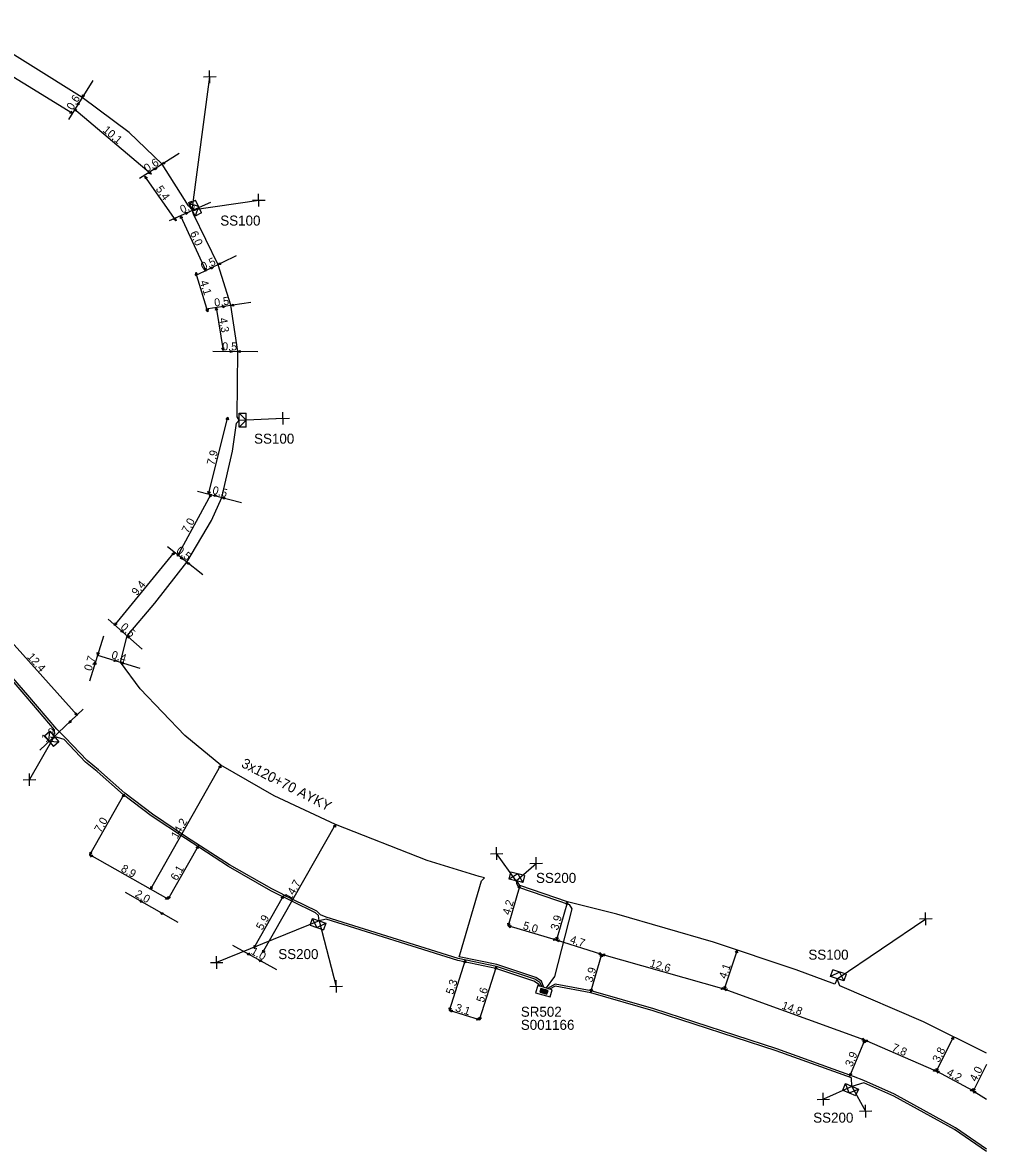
# Model space of a CAD drawing. Extents: x -762504 to -761250, y -1152974 to -1152253.
# Drawn here: x -761345.8 to -761250, y -1152498.2 to -1152386 of the extents above; entities that cross this region are included whole.
import ezdxf

# ---------------------------------------------------------------- set-up
doc = ezdxf.new("R2010")
doc.units = 0
for name, color, linetype in [('Vrstva 28', 7, 'Continuous'), ('Vrstva 29', 7, 'Continuous'), ('Vrstva 30', 7, 'Continuous'), ('Vrstva 31', 7, 'Continuous'), ('Vrstva 33', 7, 'Continuous'), ('Vrstva 34', 7, 'Continuous'), ('Vrstva 40', 7, 'Continuous'), ('Vrstva 5', 7, 'Continuous'), ('Vrstva 59', 7, 'Continuous'), ('Vrstva 6', 7, 'Continuous')]:
    doc.layers.add(name, color=color, linetype=linetype)

msp = doc.modelspace()

# ---------------------------------------------------------------- linework, layer by layer
at = {"layer": 'Vrstva 28'}
for points in [[(-761294.578, -1152481.71), (-761294.785, -1152482.431)], [(-761293.136, -1152482.124), (-761294.578, -1152481.71)], [(-761294.271, -1152481.989), (-761294.375, -1152482.352)], [(-761294.238, -1152482.047), (-761294.317, -1152482.32)], [(-761293.556, -1152482.194), (-761294.271, -1152481.989)], [(-761294.206, -1152482.106), (-761294.258, -1152482.288)], [(-761293.614, -1152482.227), (-761294.238, -1152482.047)], [(-761293.672, -1152482.259), (-761294.206, -1152482.106)], [(-761293.343, -1152482.845), (-761293.136, -1152482.124)], [(-761294.785, -1152482.431), (-761293.343, -1152482.845)], [(-761294.375, -1152482.352), (-761293.66, -1152482.557)], [(-761294.317, -1152482.32), (-761293.692, -1152482.499)], [(-761294.258, -1152482.288), (-761293.724, -1152482.441)], [(-761294.174, -1152482.164), (-761294.2, -1152482.255)], [(-761294.2, -1152482.255), (-761293.757, -1152482.382)], [(-761293.731, -1152482.291), (-761294.174, -1152482.164)], [(-761294.147, -1152482.221), (-761293.784, -1152482.325)], [(-761293.757, -1152482.382), (-761293.731, -1152482.291)], [(-761293.724, -1152482.441), (-761293.672, -1152482.259)], [(-761293.692, -1152482.499), (-761293.614, -1152482.227)], [(-761293.66, -1152482.557), (-761293.556, -1152482.194)]]:
    msp.add_lwpolyline(points, dxfattribs=at)
at = {"layer": 'Vrstva 31'}
for points in [[(-761327.972, -1152404.945), (-761328.602, -1152405.252), (-761329.215, -1152403.993), (-761328.586, -1152403.686)], [(-761328.279, -1152404.316), (-761329.215, -1152403.993)], [(-761328.279, -1152404.316), (-761328.602, -1152405.252)], [(-761327.972, -1152404.945), (-761328.586, -1152403.686)], [(-761323.54, -1152425.543), (-761324.24, -1152424.843)], [(-761323.54, -1152426.243), (-761324.24, -1152426.243), (-761324.24, -1152424.843), (-761323.54, -1152424.843)], [(-761323.54, -1152426.243), (-761323.54, -1152424.843)], [(-761323.54, -1152425.543), (-761324.24, -1152426.243)], [(-761343.6, -1152456.899), (-761343.071, -1152456.44), (-761342.153, -1152457.496), (-761342.681, -1152457.956)], [(-761343.6, -1152456.899), (-761342.681, -1152457.956)], [(-761343.141, -1152457.427), (-761343.071, -1152456.44)], [(-761343.141, -1152457.427), (-761342.153, -1152457.496)], [(-761295.879, -1152470.79), (-761296.048, -1152471.47), (-761297.406, -1152471.131), (-761297.237, -1152470.452)], [(-761296.558, -1152470.621), (-761297.406, -1152471.131)], [(-761295.879, -1152470.79), (-761297.237, -1152470.452)], [(-761296.558, -1152470.621), (-761296.048, -1152471.47)], [(-761317.183, -1152475.713), (-761316.955, -1152475.051), (-761315.631, -1152475.507), (-761315.859, -1152476.169)], [(-761316.521, -1152475.941), (-761316.955, -1152475.051)], [(-761317.183, -1152475.713), (-761315.859, -1152476.169)], [(-761316.521, -1152475.941), (-761315.631, -1152475.507)], [(-761263.945, -1152480.591), (-761264.161, -1152481.257), (-761265.493, -1152480.824), (-761265.276, -1152480.158)], [(-761264.611, -1152480.375), (-761265.493, -1152480.824)], [(-761263.945, -1152480.591), (-761265.276, -1152480.158)], [(-761264.611, -1152480.375), (-761264.161, -1152481.257)], [(-761264.281, -1152492.1), (-761264.007, -1152491.456), (-761262.718, -1152492.003), (-761262.992, -1152492.647)], [(-761264.281, -1152492.1), (-761262.992, -1152492.647)], [(-761263.636, -1152492.374), (-761264.007, -1152491.456)], [(-761263.636, -1152492.374), (-761262.718, -1152492.003)]]:
    msp.add_lwpolyline(points, dxfattribs=at)
at = {"layer": 'Vrstva 34'}
for points in [[(-761327.159, -1152392.035), (-761327.181, -1152390.785)], [(-761327.795, -1152391.421), (-761326.545, -1152391.399)], [(-761322.289, -1152404.295), (-761322.311, -1152403.045)], [(-761322.925, -1152403.681), (-761321.675, -1152403.659)], [(-761319.869, -1152425.975), (-761319.891, -1152424.725)], [(-761320.505, -1152425.361), (-761319.255, -1152425.339)], [(-761345.059, -1152461.875), (-761345.081, -1152460.625)], [(-761345.695, -1152461.261), (-761344.445, -1152461.239)], [(-761299.285, -1152468.611), (-761298.035, -1152468.589)], [(-761298.649, -1152469.225), (-761298.671, -1152467.975)], [(-761295.355, -1152469.581), (-761294.105, -1152469.559)], [(-761294.719, -1152470.195), (-761294.741, -1152468.945)], [(-761256.655, -1152475.081), (-761255.405, -1152475.059)], [(-761256.019, -1152475.695), (-761256.041, -1152474.445)], [(-761327.105, -1152479.431), (-761325.855, -1152479.409)], [(-761326.469, -1152480.045), (-761326.491, -1152478.795)], [(-761315.225, -1152481.801), (-761313.975, -1152481.779)], [(-761314.589, -1152482.415), (-761314.611, -1152481.165)], [(-761266.825, -1152493.021), (-761265.575, -1152492.999)], [(-761266.189, -1152493.635), (-761266.211, -1152492.385)], [(-761262.625, -1152494.191), (-761261.375, -1152494.169)], [(-761261.989, -1152494.805), (-761262.011, -1152493.555)]]:
    msp.add_lwpolyline(points, dxfattribs=at)
at = {"layer": 'Vrstva 40'}
for points in [[(-761340.81, -1152395.06), (-761355.53, -1152386.03)], [(-761338.77, -1152391.77), (-761341.19, -1152395.65)], [(-761332.98, -1152401.1), (-761340.67, -1152394.6)], [(-761330.2, -1152399.04), (-761334.13, -1152401.52)], [(-761330.51, -1152405.72), (-761333.62, -1152401.28)], [(-761331.15, -1152405.69), (-761327.06, -1152403.89)], [(-761330.07, -1152405.23), (-761327.56, -1152410.71)], [(-761324.53, -1152409.22), (-761328.61, -1152411.2)], [(-761327.34, -1152414.76), (-761328.56, -1152410.87)], [(-761323.1, -1152413.84), (-761327.57, -1152414.51)], [(-761326.53, -1152414.35), (-761325.83, -1152418.62)], [(-761322.39, -1152418.74), (-761326.87, -1152418.7)], [(-761327.3, -1152432.87), (-761325.36, -1152425.25)], [(-761328.38, -1152432.6), (-761324.02, -1152433.7)], [(-761330.37, -1152439.05), (-761327.03, -1152432.88)], [(-761327.86, -1152440.89), (-761331.37, -1152438.12)], [(-761336.62, -1152445.93), (-761330.67, -1152438.65)], [(-761340.33, -1152454.86), (-761348.63, -1152445.65)], [(-761337.25, -1152445.32), (-761333.88, -1152448.29)], [(-761337.72, -1152446.98), (-761339.1, -1152451.45)], [(-761338.31, -1152448.89), (-761334.11, -1152450.18)], [(-761339.73, -1152454.26), (-761344.04, -1152458.33)], [(-761333.05, -1152472.15), (-761326.05, -1152459.81)], [(-761339.09, -1152468.73), (-761335.66, -1152462.68)], [(-761321.91, -1152478.47), (-761314.66, -1152465.7)], [(-761331.31, -1152473.14), (-761328.3, -1152467.83)], [(-761331.31, -1152473.14), (-761339.09, -1152468.73)], [(-761296.36, -1152471.77), (-761297.52, -1152475.77)], [(-761330.31, -1152475.44), (-761335.54, -1152472.47)], [(-761322.78, -1152477.98), (-761319.85, -1152472.81)], [(-761291.62, -1152473.4), (-761292.72, -1152477.17)], [(-761292.73, -1152477.2), (-761297.53, -1152475.79)], [(-761288.2, -1152478.61), (-761292.72, -1152477.19)], [(-761324.91, -1152477.7), (-761320.52, -1152480.11)], [(-761289.29, -1152482.34), (-761288.2, -1152478.59)], [(-761276.05, -1152482.08), (-761288.2, -1152478.61)], [(-761274.75, -1152478.19), (-761276.04, -1152482.07)], [(-761303.34, -1152484.19), (-761301.75, -1152479.17)], [(-761300.36, -1152485.13), (-761298.68, -1152479.82)], [(-761262.09, -1152487.13), (-761276.04, -1152482.07)], [(-761300.36, -1152485.13), (-761303.34, -1152484.19)], [(-761263.57, -1152490.71), (-761262.09, -1152487.12)], [(-761254.99, -1152490.23), (-761262.09, -1152487.14)], [(-761253.26, -1152486.81), (-761254.99, -1152490.23)], [(-761250, -1152489.56), (-761251.33, -1152492.2)], [(-761251.32, -1152492.18), (-761254.97, -1152490.2)], [(-761250, -1152493.02), (-761251.33, -1152492.2)]]:
    msp.add_lwpolyline(points, dxfattribs=at)
for points in [[(-761339.832, -1152393.472), (-761339.793, -1152393.205), (-761339.614, -1152393.313)], [(-761340.671, -1152394.598), (-761340.414, -1152394.677), (-761340.548, -1152394.838)], [(-761340.128, -1152393.948), (-761340.166, -1152394.215), (-761340.346, -1152394.107)], [(-761340.808, -1152395.062), (-761341.075, -1152395.023), (-761340.967, -1152394.844)], [(-761331.892, -1152400.111), (-761331.74, -1152399.888), (-761331.627, -1152400.064)], [(-761333.621, -1152401.278), (-761333.391, -1152401.418), (-761333.56, -1152401.54)], [(-761332.978, -1152401.101), (-761333.235, -1152401.022), (-761333.101, -1152400.861)], [(-761332.428, -1152400.448), (-761332.579, -1152400.671), (-761332.693, -1152400.496)], [(-761328.893, -1152404.701), (-761328.708, -1152404.505), (-761328.623, -1152404.695)], [(-761330.509, -1152405.722), (-761330.739, -1152405.583), (-761330.57, -1152405.46)], [(-761330.07, -1152405.227), (-761329.871, -1152405.408), (-761330.06, -1152405.497)], [(-761329.318, -1152404.889), (-761329.502, -1152405.086), (-761329.587, -1152404.895)], [(-761326.808, -1152410.329), (-761326.985, -1152410.532), (-761327.077, -1152410.344)], [(-761326.332, -1152410.091), (-761326.154, -1152409.888), (-761326.063, -1152410.076)], [(-761328.561, -1152410.867), (-761328.385, -1152411.072), (-761328.583, -1152411.136)], [(-761327.56, -1152410.713), (-761327.759, -1152410.531), (-761327.57, -1152410.443)], [(-761327.34, -1152414.762), (-761327.516, -1152414.558), (-761327.317, -1152414.494)], [(-761326.531, -1152414.348), (-761326.384, -1152414.575), (-761326.59, -1152414.611)], [(-761325.588, -1152414.219), (-761325.817, -1152414.362), (-761325.85, -1152414.155)], [(-761325.082, -1152414.14), (-761324.853, -1152413.998), (-761324.82, -1152414.205)], [(-761325.83, -1152418.623), (-761325.976, -1152418.396), (-761325.77, -1152418.36)], [(-761324.868, -1152418.72), (-761325.116, -1152418.825), (-761325.116, -1152418.616)], [(-761324.393, -1152418.72), (-761324.144, -1152418.615), (-761324.144, -1152418.824)], [(-761325.359, -1152425.248), (-761325.318, -1152425.514), (-761325.52, -1152425.464)], [(-761327.301, -1152432.872), (-761327.343, -1152432.606), (-761327.14, -1152432.657)], [(-761327.028, -1152432.878), (-761327.053, -1152433.146), (-761327.237, -1152433.048)], [(-761326.438, -1152433.091), (-761326.704, -1152433.132), (-761326.654, -1152432.929)], [(-761325.962, -1152433.209), (-761325.696, -1152433.168), (-761325.746, -1152433.371)], [(-761330.669, -1152438.648), (-761330.744, -1152438.907), (-761330.906, -1152438.775)], [(-761330.371, -1152439.052), (-761330.347, -1152438.783), (-761330.162, -1152438.881)], [(-761329.798, -1152439.362), (-761330.059, -1152439.291), (-761329.93, -1152439.127)], [(-761329.432, -1152439.648), (-761329.172, -1152439.719), (-761329.3, -1152439.884)], [(-761336.622, -1152445.932), (-761336.547, -1152445.673), (-761336.384, -1152445.804)], [(-761335.748, -1152446.642), (-761336.004, -1152446.557), (-761335.867, -1152446.4)], [(-761335.382, -1152446.968), (-761335.126, -1152447.052), (-761335.263, -1152447.21)], [(-761338.509, -1152449.527), (-761338.482, -1152449.796), (-761338.681, -1152449.734)], [(-761338.311, -1152448.892), (-761338.338, -1152448.624), (-761338.139, -1152448.685)], [(-761336.398, -1152449.471), (-761336.666, -1152449.498), (-761336.605, -1152449.299)], [(-761336.022, -1152449.589), (-761335.754, -1152449.562), (-761335.815, -1152449.762)], [(-761340.328, -1152454.862), (-761340.574, -1152454.751), (-761340.422, -1152454.609)], [(-761341.182, -1152455.632), (-761341.075, -1152455.384), (-761340.93, -1152455.534)], [(-761342.588, -1152456.949), (-761342.695, -1152457.197), (-761342.84, -1152457.046)], [(-761326.049, -1152459.808), (-761326.078, -1152460.076), (-761326.261, -1152459.975)], [(-761335.659, -1152462.678), (-761335.688, -1152462.946), (-761335.87, -1152462.845)], [(-761314.658, -1152465.698), (-761314.687, -1152465.966), (-761314.87, -1152465.865)], [(-761339.091, -1152468.732), (-761339.062, -1152468.464), (-761338.88, -1152468.565)], [(-761328.299, -1152467.828), (-761328.328, -1152468.096), (-761328.511, -1152467.995)], [(-761339.092, -1152468.728), (-761338.824, -1152468.758), (-761338.925, -1152468.94)], [(-761333.051, -1152472.152), (-761333.022, -1152471.884), (-761332.839, -1152471.985)], [(-761296.359, -1152471.768), (-761296.327, -1152472.035), (-761296.528, -1152471.978)], [(-761331.308, -1152473.142), (-761331.576, -1152473.112), (-761331.475, -1152472.93)], [(-761331.311, -1152473.142), (-761331.282, -1152472.874), (-761331.099, -1152472.975)], [(-761319.849, -1152472.808), (-761319.878, -1152473.076), (-761320.061, -1152472.974)], [(-761333.798, -1152473.462), (-761334.066, -1152473.432), (-761333.965, -1152473.25)], [(-761291.619, -1152473.398), (-761291.587, -1152473.665), (-761291.788, -1152473.608)], [(-761332.052, -1152474.449), (-761331.784, -1152474.478), (-761331.885, -1152474.66)], [(-761297.521, -1152475.772), (-761297.552, -1152475.505), (-761297.352, -1152475.562)], [(-761297.532, -1152475.789), (-761297.264, -1152475.757), (-761297.322, -1152475.958)], [(-761292.728, -1152477.201), (-761292.995, -1152477.233), (-761292.938, -1152477.032)], [(-761292.721, -1152477.172), (-761292.753, -1152476.905), (-761292.552, -1152476.962)], [(-761292.723, -1152477.189), (-761292.454, -1152477.162), (-761292.515, -1152477.362)], [(-761323.157, -1152478.671), (-761323.426, -1152478.647), (-761323.328, -1152478.462)], [(-761322.781, -1152477.982), (-761322.752, -1152477.714), (-761322.569, -1152477.815)], [(-761321.911, -1152478.472), (-761321.882, -1152478.204), (-761321.699, -1152478.306)], [(-761288.198, -1152478.611), (-761288.466, -1152478.639), (-761288.405, -1152478.439)], [(-761288.199, -1152478.588), (-761288.167, -1152478.856), (-761288.368, -1152478.798)], [(-761288.202, -1152478.61), (-761287.935, -1152478.573), (-761287.989, -1152478.775)], [(-761274.749, -1152478.188), (-761274.727, -1152478.457), (-761274.926, -1152478.392)], [(-761322.282, -1152479.149), (-761322.013, -1152479.173), (-761322.112, -1152479.358)], [(-761301.749, -1152479.168), (-761301.722, -1152479.436), (-761301.922, -1152479.375)], [(-761298.68, -1152479.818), (-761298.652, -1152480.086), (-761298.852, -1152480.025)], [(-761289.291, -1152482.342), (-761289.323, -1152482.075), (-761289.122, -1152482.132)], [(-761276.047, -1152482.081), (-761276.315, -1152482.118), (-761276.261, -1152481.916)], [(-761276.041, -1152482.072), (-761276.064, -1152481.804), (-761275.865, -1152481.868)], [(-761276.043, -1152482.069), (-761275.774, -1152482.051), (-761275.842, -1152482.248)], [(-761303.341, -1152484.193), (-761303.368, -1152483.924), (-761303.168, -1152483.986)], [(-761303.342, -1152484.189), (-761303.074, -1152484.161), (-761303.135, -1152484.361)], [(-761300.358, -1152485.131), (-761300.626, -1152485.158), (-761300.565, -1152484.958)], [(-761300.361, -1152485.132), (-761300.388, -1152484.864), (-761300.188, -1152484.925)], [(-761262.088, -1152487.131), (-761262.357, -1152487.148), (-761262.289, -1152486.951)], [(-761262.089, -1152487.118), (-761262.085, -1152487.387), (-761262.279, -1152487.309)], [(-761262.092, -1152487.139), (-761261.823, -1152487.14), (-761261.904, -1152487.332)], [(-761253.258, -1152486.808), (-761253.273, -1152487.077), (-761253.461, -1152486.985)], [(-761254.992, -1152490.232), (-761254.977, -1152489.963), (-761254.789, -1152490.054)], [(-761263.571, -1152490.712), (-761263.575, -1152490.442), (-761263.381, -1152490.521)], [(-761254.988, -1152490.231), (-761255.258, -1152490.23), (-761255.176, -1152490.038)], [(-761254.973, -1152490.199), (-761254.704, -1152490.223), (-761254.802, -1152490.408)], [(-761251.318, -1152492.182), (-761251.587, -1152492.157), (-761251.489, -1152491.973)], [(-761251.332, -1152492.202), (-761251.317, -1152491.933), (-761251.129, -1152492.025)], [(-761251.332, -1152492.199), (-761251.065, -1152492.237), (-761251.173, -1152492.417)]]:
    msp.add_lwpolyline(points, close=True, dxfattribs=at)
at = {"layer": 'Vrstva 5'}
for points in [[(-761293.97, -1152481.89), (-761294.22, -1152481.27), (-761294.78, -1152480.9), (-761298.63, -1152479.63), (-761302.4, -1152478.84), (-761302.31, -1152478.67), (-761300.15, -1152471.31), (-761299.86, -1152471), (-761300.41, -1152470.87), (-761305.55, -1152469.27), (-761314.66, -1152465.7), (-761320.77, -1152462.86), (-761326.05, -1152459.81), (-761329.65, -1152456.85), (-761334.07, -1152452.22), (-761336.02, -1152449.59), (-761335.38, -1152446.97), (-761332.63, -1152443.72), (-761329.43, -1152439.65), (-761327, -1152435.51), (-761325.96, -1152433.21), (-761324.91, -1152428.63), (-761324.52, -1152425.84), (-761324.24, -1152425.54), (-761324.44, -1152425.21), (-761324.39, -1152418.72), (-761325.08, -1152414.11), (-761326.33, -1152410.09), (-761328.77, -1152405.08), (-761328.91, -1152404.62), (-761329.29, -1152404.23), (-761331.89, -1152400.11), (-761335.17, -1152396.94), (-761339.83, -1152393.47), (-761350.42, -1152386.88)], [(-761294.3, -1152481.81), (-761294.5, -1152481.57), (-761294.96, -1152481.26), (-761298.73, -1152480.01), (-761302.53, -1152479.22), (-761315.61, -1152475.12), (-761316.29, -1152475.28), (-761316.35, -1152474.75), (-761316.65, -1152474.47), (-761318.94, -1152473.37), (-761321.1, -1152472.29), (-761325.29, -1152469.88), (-761329.57, -1152467.11), (-761332.99, -1152464.83), (-761335.72, -1152462.76), (-761338.36, -1152460.44), (-761339.5, -1152459.5), (-761341.64, -1152457.25), (-761342.61, -1152456.97), (-761342.58, -1152456.29), (-761345.4, -1152452.99), (-761348.42, -1152449.52)], [(-761294.15, -1152481.84), (-761294.36, -1152481.42), (-761294.87, -1152481.08), (-761298.68, -1152479.82), (-761302.49, -1152479.02), (-761315.61, -1152474.9), (-761316.15, -1152474.67), (-761316.53, -1152474.31), (-761318.86, -1152473.19), (-761321, -1152472.11), (-761325.19, -1152469.71), (-761329.46, -1152466.95), (-761332.87, -1152464.67), (-761335.6, -1152462.6), (-761338.23, -1152460.28), (-761339.36, -1152459.36), (-761341.54, -1152457.07), (-761342.36, -1152456.23), (-761345.24, -1152452.86), (-761348.26, -1152449.4)], [(-761250, -1152488.42), (-761256.25, -1152485.33), (-761264.56, -1152481.73), (-761264.83, -1152481.04), (-761265.05, -1152481.57), (-761268.9, -1152480.14), (-761277.12, -1152477.4), (-761286.71, -1152474.62), (-761291.62, -1152473.4), (-761296.36, -1152471.77), (-761296.51, -1152471.51), (-761296.73, -1152471.3), (-761296.69, -1152471.58), (-761296.5, -1152471.93), (-761291.45, -1152473.67), (-761291.19, -1152474.1), (-761292.9, -1152480.81), (-761293.74, -1152481.95)], [(-761250, -1152497.95), (-761253.08, -1152495.86), (-761259.12, -1152492.51), (-761262.19, -1152491.15), (-761263.21, -1152490.75), (-761270.84, -1152488), (-761283.06, -1152484.03), (-761289.27, -1152482.24), (-761292.84, -1152481.57), (-761293.6, -1152482)], [(-761250, -1152498.19), (-761253.18, -1152496.02), (-761259.21, -1152492.69), (-761262.19, -1152491.37), (-761263.36, -1152491.73), (-761263.41, -1152490.89), (-761270.9, -1152488.19), (-761283.12, -1152484.23), (-761289.31, -1152482.44), (-761292.84, -1152481.77), (-761293.4, -1152482.06)]]:
    msp.add_lwpolyline(points, dxfattribs=at)
at = {"layer": 'Vrstva 59'}
for points in [[(-761328.91, -1152404.62), (-761327.17, -1152391.41)], [(-761328.91, -1152404.62), (-761322.3, -1152403.67)], [(-761324.24, -1152425.54), (-761319.88, -1152425.35)], [(-761342.61, -1152456.97), (-761345.07, -1152461.25)], [(-761296.73, -1152471.3), (-761298.66, -1152468.6)], [(-761296.73, -1152471.3), (-761294.73, -1152469.57)], [(-761316.29, -1152475.28), (-761326.48, -1152479.42)], [(-761316.29, -1152475.28), (-761314.6, -1152481.79)], [(-761264.83, -1152481.04), (-761256.03, -1152475.07)], [(-761263.36, -1152491.73), (-761266.2, -1152493.01)], [(-761263.36, -1152491.73), (-761262, -1152494.18)]]:
    msp.add_lwpolyline(points, dxfattribs=at)

# ---------------------------------------------------------------- texts
at = {"layer": 'Vrstva 29'}
msp.add_text('S001166', height=0.9943, dxfattribs=at).set_placement((-761296.26, -1152486.11))
at = {"layer": 'Vrstva 30'}
msp.add_text('SR502', height=0.9943, dxfattribs=at).set_placement((-761296.26, -1152484.81))
at = {"layer": 'Vrstva 33'}
for s, p in [('SS100', (-761326.12, -1152406.2)), ('SS100', (-761322.76, -1152427.87)), ('SS200', (-761294.75, -1152471.51)), ('SS200', (-761320.36, -1152479.08)), ('SS100', (-761267.69, -1152479.14)), ('SS200', (-761267.21, -1152495.33))]:
    msp.add_text(s, height=0.9943, dxfattribs=at).set_placement(p)
at = {"layer": 'Vrstva 40'}
for s, rotation, p in [('0,6', 58.10645, (-761340.79, -1152394.79)), ('10,1', 319.81593, (-761337.86, -1152396.81)), ('0,6', 32.25656, (-761333.4, -1152400.92)), ('5,4', 305.07143, (-761332.57, -1152402.57)), ('0,5', 23.73629, (-761329.91, -1152405.01)), ('6,0', 294.58961, (-761329.15, -1152406.95)), ('0,5', 25.96649, (-761327.82, -1152410.68)), ('4,1', 287.39061, (-761328.15, -1152411.77)), ('0,5', 8.51543, (-761326.66, -1152414.26)), ('4,3', 279.3584, (-761326.24, -1152415.42)), ('0,5', 359.55579, (-761325.93, -1152418.59)), ('7,9', 75.72284, (-761326.71, -1152430.06)), ('0,5', 345.75654, (-761326.96, -1152432.83)), ('7,0', 61.60692, (-761329.31, -1152436.84)), ('0,5', 321.82553, (-761330.56, -1152438.61)), ('9,4', 50.75581, (-761334.41, -1152443.03)), ('0,5', 318.52764, (-761336.1, -1152446.18)), ('0,4', 342.95936, (-761337, -1152449.17)), ('12,4', 312.01111, (-761345.36, -1152449.09)), ('0,7', 72.93868, (-761338.93, -1152450.51)), ('1,9', 43.29459, (-761343.44, -1152457.59)), ('7,0', 60.42849, (-761338, -1152466.57)), ('14,2', 60.42889, (-761330.38, -1152467.19)), ('8,9', 330.4245, (-761336.06, -1152470.31)), ('6,1', 60.42876, (-761330.43, -1152471.35)), ('14,7', 60.42882, (-761319.11, -1152473.3)), ('2,0', 330.42514, (-761334.66, -1152472.83)), ('4,2', 73.77806, (-761297.35, -1152474.75)), ('5,9', 60.42916, (-761321.94, -1152476.26)), ('5,0', 343.67849, (-761296.11, -1152476.08)), ('3,9', 73.77703, (-761292.58, -1152476.27)), ('4,7', 342.54039, (-761291.44, -1152477.46)), ('1,0', 331.2476, (-761323.15, -1152478.53)), ('12,6', 344.06408, (-761283.5, -1152479.83)), ('4,1', 71.54504, (-761275.85, -1152481.1)), ('3,9', 73.7773, (-761289.16, -1152481.45)), ('5,3', 72.45623, (-761302.98, -1152482.66)), ('5,6', 72.45648, (-761299.95, -1152483.45)), ('3,1', 342.45959, (-761302.83, -1152484.23)), ('14,8', 340.04888, (-761270.4, -1152483.99)), ('7,8', 336.45979, (-761259.46, -1152488.15)), ('3,9', 67.51237, (-761263.35, -1152489.85)), ('3,8', 63.22969, (-761254.71, -1152489.41)), ('4,0', 63.23122, (-761251.02, -1152491.32)), ('4,2', 331.59514, (-761254.02, -1152490.58))]:
    msp.add_text(s, height=0.7954, rotation=rotation, dxfattribs=at).set_placement(p)
at = {"layer": 'Vrstva 6'}
msp.add_text('3x120+70 AYKY', height=0.99429, rotation=332.8787, dxfattribs=at).set_placement((-761324.11, -1152459.95))

doc.saveas('drawing.dxf')
